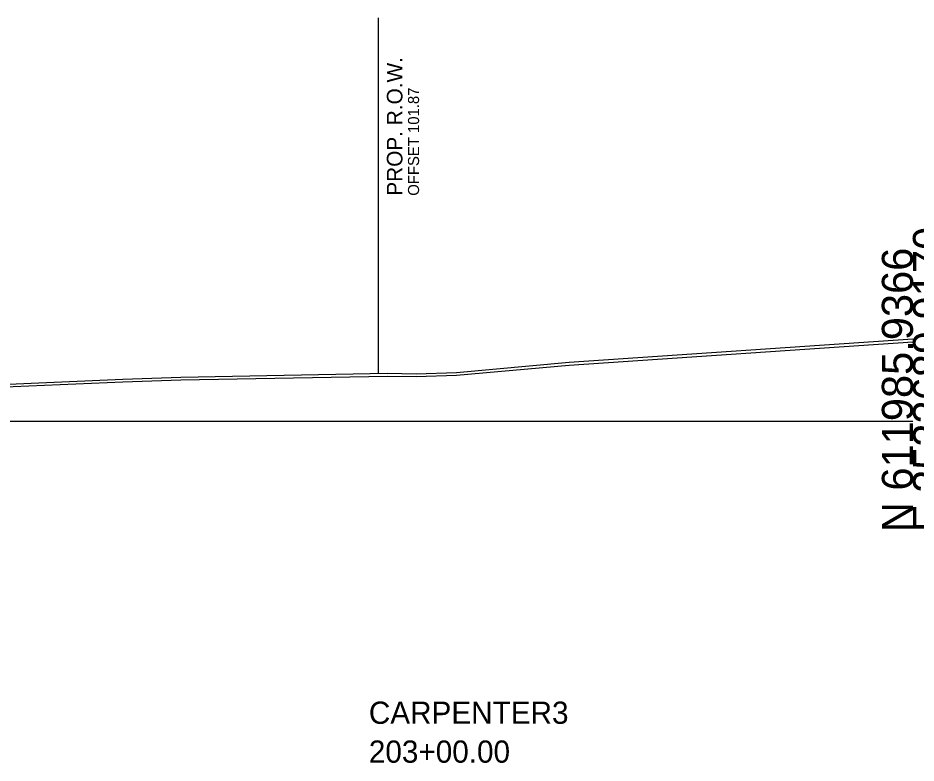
# Model space of a CAD drawing. Extents: x -120 to 2876, y -25 to 8560.
# Drawn here: x 219.4 to 300.3, y 5969.2 to 6036.3 of the extents above; entities that cross this region are included whole.
import ezdxf

# ---------------------------------------------------------------- set-up
doc = ezdxf.new("R2010")
doc.units = 0
for name, color, linetype in [('DESIGN - ROW - Right-of-Way and Easement Labels', 7, 'Continuous'), ('DESIGN - ROW - Right-of-Way Linework', 7, 'Continuous'), ('DESIGN - SHEET - Light Grid', 7, 'Continuous'), ('DESIGN - TYPICAL - Warning Text', 7, 'Continuous'), ('SURVEY - GROUND - Bottom of Topsoil Layer', 7, 'Continuous'), ('SURVEY - GROUND - Top of Ground', 7, 'Continuous')]:
    doc.layers.add(name, color=color, linetype=linetype)

msp = doc.modelspace()

# ---------------------------------------------------------------- linework, layer by layer
at = {"layer": 'DESIGN - ROW - Right-of-Way Linework'}
msp.add_line((251.874, 6004.285), (251.874, 6036.285), dxfattribs=at)
at = {"layer": 'DESIGN - SHEET - Light Grid'}
msp.add_line((150, 6000), (300, 6000), dxfattribs=at)
at = {"layer": 'SURVEY - GROUND - Bottom of Topsoil Layer'}
for p, q in [((269.045, 6005.047), (300, 6007.147)), ((258.887, 6004.137), (269.045, 6005.047)), ((228.854, 6003.532), (234.074, 6003.707)), ((234.074, 6003.707), (252.68, 6004.049)), ((252.68, 6004.049), (255.249, 6004.009)), ((255.249, 6004.009), (258.887, 6004.137)), ((217.145, 6003.021), (228.854, 6003.532))]:
    msp.add_line(p, q, dxfattribs=at)
at = {"layer": 'SURVEY - GROUND - Top of Ground'}
msp.add_lwpolyline([(217.145, 6003.271), (228.854, 6003.782), (234.074, 6003.957), (252.68, 6004.299), (255.249, 6004.259), (258.887, 6004.387), (269.045, 6005.297), (300, 6007.397)], dxfattribs=at)

# ---------------------------------------------------------------- texts
at = {"layer": 'DESIGN - ROW - Right-of-Way and Easement Labels'}
for s, height, p in [('PROP. R.O.W.', 1.4, (254.024, 6020.285)), ('OFFSET 101.87', 1, (255.524, 6020.285))]:
    msp.add_text(s, height=height, rotation=90, dxfattribs=at).set_placement(p)
at = {"layer": 'DESIGN - SHEET - Light Grid'}
for s, p in [('E 2533689.9170', (302.8, 5990)), ('N 611985.9366', (300, 5990))]:
    msp.add_text(s, height=2.8, rotation=90, dxfattribs=at).set_placement(p)
at = {"layer": 'DESIGN - TYPICAL - Warning Text'}
for s, p in [('CARPENTER3', (251, 5972.75)), ('203+00.00', (251, 5969.25))]:
    msp.add_text(s, height=2, dxfattribs=at).set_placement(p)

doc.saveas('drawing.dxf')
